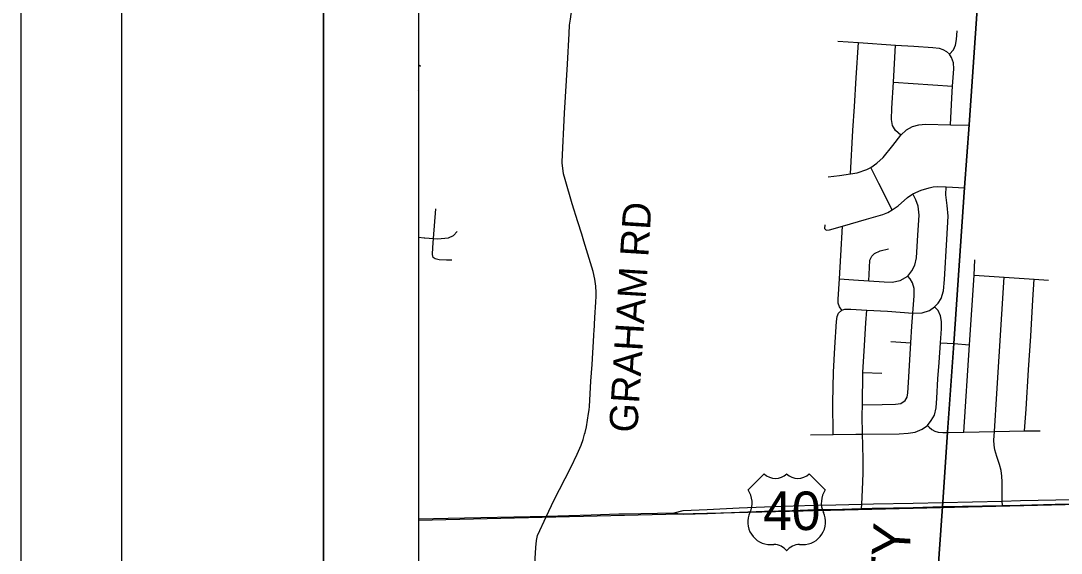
# Model space of a CAD drawing. Extents: x 1880545 to 1948545, y 79309 to 723051.
# Drawn here: x 1880545 to 1890853, y 711978 to 717259 of the extents above; entities that cross this region are included whole.
import ezdxf

# ---------------------------------------------------------------- set-up
doc = ezdxf.new("R2010")
doc.units = 0
for name, color, linetype in [('GM_X_City_Street', 7, 'Continuous'), ('GM_X_County', 7, 'Continuous'), ('GM_X_County_Road', 7, 'Continuous'), ('GM_X_County_Text', 7, 'Continuous'), ('GM_X_Rail_Line', 7, 'Continuous'), ('GM_X_Township', 7, 'Continuous'), ('GM_X_US_Location', 7, 'Continuous'), ('GM_X_US_Route', 7, 'Continuous'), ('GM_X_US_Shield', 7, 'Continuous'), ('SH_Border', 7, 'Continuous'), ('SH_Cut_Line', 7, 'Continuous'), ('SH_Text', 7, 'Continuous')]:
    doc.layers.add(name, color=color, linetype=linetype)

msp = doc.modelspace()

# ---------------------------------------------------------------- linework, layer by layer
at = {"layer": 'GM_X_City_Street'}
for p, q in [((1884485, 716824), (1884504, 716810)), ((1884485, 716572), (1884490, 716578)), ((1889192, 716650), (1889778, 716611)), ((1884633, 715100), (1884658, 715394)), ((1889166, 714079), (1889365, 714065)), ((1889658, 714064), (1889790, 714057)), ((1889790, 714057), (1889944, 714045)), ((1888887, 713769), (1889076, 713763))]:
    msp.add_line(p, q, dxfattribs=at)
for points in [[(1889756, 716227), (1889771, 716494), (1889778, 716611), (1889790, 716782), (1889785, 716843), (1889767, 716893), (1889746, 716927), (1889785, 716970), (1889807, 717017), (1889817, 717073), (1889824, 717159)], [(1888640, 717056), (1888845, 717042), (1889213, 717018), (1889393, 717007), (1889582, 716993), (1889643, 716987), (1889682, 716974), (1889716, 716954), (1889746, 716927)], [(1888765, 715741), (1888790, 716169), (1888805, 716408), (1888823, 716694), (1888845, 717042)], [(1889264, 716123), (1889213, 716169), (1889183, 716220), (1889171, 716281), (1889174, 716391), (1889192, 716650), (1889213, 717018)], [(1888544, 715710), (1888657, 715725), (1888765, 715741), (1888832, 715752), (1888927, 715784), (1888968, 715803), (1889027, 715845), (1889089, 715903), (1889186, 716023), (1889264, 716123), (1889322, 716176), (1889380, 716209), (1889442, 716227), (1889508, 716234), (1889756, 716227), (1889941, 716223)], [(1889177, 715382), (1889046, 715645), (1888968, 715803)], [(1888510, 715236), (1888509, 715200), (1888526, 715183), (1888558, 715184), (1888688, 715221), (1888923, 715291), (1889087, 715338), (1889137, 715358), (1889177, 715382), (1889239, 715423), (1889329, 715507), (1889385, 715542), (1889465, 715580), (1889544, 715602), (1889586, 715611), (1889629, 715614), (1889715, 715613), (1889898, 715601)], [(1889309, 713493), (1889326, 713525), (1889333, 713568), (1889341, 713670), (1889365, 714065), (1889375, 714229), (1889385, 714359), (1889395, 714529), (1889396, 714603), (1889380, 714661), (1889356, 714699), (1889333, 714727), (1889374, 714777), (1889402, 714834), (1889419, 714908), (1889433, 715132), (1889445, 715332), (1889436, 715421), (1889414, 715484), (1889385, 715542)], [(1889528, 713245), (1889566, 713293), (1889597, 713348), (1889615, 713421), (1889621, 713514), (1889632, 713706), (1889643, 713870), (1889658, 714064), (1889666, 714203), (1889668, 714276), (1889659, 714332), (1889633, 714384), (1889599, 714423), (1889634, 714459), (1889664, 714503), (1889687, 714581), (1889696, 714691), (1889721, 715088), (1889733, 715321), (1889723, 715425), (1889712, 715533), (1889715, 715613)], [(1884485, 715114), (1884542, 715107), (1884547, 715106), (1884633, 715100), (1884674, 715097), (1884784, 715107), (1884831, 715129), (1884868, 715169)], [(1888594, 713154), (1888590, 713474), (1888596, 713772), (1888610, 714017), (1888627, 714277), (1888633, 714325), (1888647, 714358), (1888679, 714388), (1888657, 714423), (1888644, 714458), (1888642, 714498), (1888658, 714699), (1888670, 714931), (1888688, 715221)], [(1884817, 714885), (1884763, 714885), (1884689, 714888), (1884650, 714897), (1884632, 714912), (1884625, 714942), (1884626, 715010), (1884633, 715100)], [(1888947, 714680), (1888953, 714812), (1888958, 714883), (1888976, 714925), (1889005, 714950), (1889059, 714977), (1889143, 714996)], [(1889889, 713179), (1889944, 714045), (1889990, 714736), (1889998, 714889)], [(1888658, 714699), (1888795, 714689), (1888947, 714680), (1889100, 714669), (1889178, 714667), (1889258, 714684), (1889333, 714727)], [(1889990, 714736), (1890288, 714716), (1890586, 714696), (1890727, 714685)], [(1890271, 712452), (1890269, 712494), (1890268, 712686), (1890265, 712742), (1890258, 712798), (1890243, 712857), (1890216, 712936), (1890197, 713002), (1890189, 713051), (1890186, 713098), (1890188, 713141), (1890191, 713186), (1890215, 713563), (1890288, 714716)], [(1890491, 713190), (1890505, 713405), (1890530, 713795), (1890553, 714132), (1890572, 714491), (1890586, 714696)], [(1888679, 714388), (1888709, 714397), (1888768, 714400), (1888927, 714388), (1889132, 714378), (1889385, 714359), (1889475, 714363), (1889548, 714386), (1889599, 714423)], [(1888886, 713160), (1888881, 713343), (1888883, 713450), (1888887, 713769), (1888903, 714038), (1888918, 714264), (1888927, 714388)], [(1888883, 713450), (1889078, 713452), (1889213, 713455), (1889266, 713463), (1889309, 713493)], [(1888370, 713152), (1888594, 713154), (1888820, 713160), (1888886, 713160), (1889249, 713163), (1889336, 713167), (1889406, 713177), (1889475, 713209), (1889528, 713245), (1889544, 713228), (1889570, 713205), (1889602, 713188), (1889635, 713178), (1889681, 713174), (1889729, 713175)], [(1889729, 713175), (1889889, 713179), (1890191, 713186), (1890491, 713190), (1890644, 713193)], [(1888874, 712420), (1888877, 712464), (1888885, 712605), (1888891, 712771), (1888890, 712902), (1888888, 713052), (1888886, 713160)]]:
    msp.add_lwpolyline(points, dxfattribs=at)
at = {"layer": 'GM_X_County'}
msp.add_lwpolyline([(1891843, 720212), (1891817, 719823), (1890200, 719967), (1890150, 719243), (1889940, 716226), (1889896, 715604), (1889789, 714059), (1889789, 714057), (1889728, 713178), (1889728, 713177), (1889680, 712485), (1889677, 712442), (1889513, 710095), (1889456, 709272), (1889272, 706620), (1886741, 706793), (1884485, 706947)], dxfattribs=at)
at = {"layer": 'GM_X_County_Road'}
for points in [[(1885910, 715859), (1885931, 716341), (1885961, 716830), (1885977, 717132), (1885983, 717214), (1885990, 717276), (1885998, 717324), (1886014, 717394), (1886028, 717448), (1886144, 717890), (1886191, 718072), (1886206, 718189), (1886290, 718819), (1886327, 719099), (1886346, 719310)], [(1886102, 715143), (1886064, 715266), (1886009, 715444), (1885939, 715686), (1885923, 715741), (1885916, 715798), (1885910, 715848), (1885910, 715859)], [(1886245, 714528), (1886246, 714565), (1886243, 714628), (1886233, 714695), (1886215, 714773), (1886124, 715072), (1886102, 715143)], [(1886224, 714158), (1886225, 714178), (1886232, 714316), (1886243, 714469), (1886245, 714528)], [(1886131, 713159), (1886135, 713174), (1886151, 713232), (1886161, 713297), (1886171, 713362), (1886176, 713400), (1886178, 713432), (1886193, 713684), (1886206, 713850), (1886222, 714138), (1886224, 714158)], [(1885752, 712346), (1885826, 712499), (1885996, 712828), (1886059, 712960), (1886096, 713049), (1886117, 713107), (1886131, 713159)], [(1885497, 709679), (1885500, 709732), (1885560, 710632), (1885590, 711101), (1885614, 711485), (1885625, 711631), (1885630, 711768), (1885647, 712035), (1885654, 712104), (1885664, 712154), (1885752, 712346)]]:
    msp.add_lwpolyline(points, dxfattribs=at)
at = {"layer": 'GM_X_Rail_Line'}
msp.add_line((1884485, 712304), (1889656, 712431), dxfattribs=at)
msp.add_lwpolyline([(1889656, 712431), (1890757, 712458), (1898417, 712647), (1903434, 712741), (1904816, 712771), (1913576, 712916), (1914801, 712916), (1920019, 712995), (1921942, 713063), (1924553, 713124), (1928206, 713206)], dxfattribs=at)
at = {"layer": 'GM_X_Township'}
for points in [[(1886104, 720212), (1886445, 720189), (1890200, 719967), (1890150, 719243), (1889940, 716226), (1889896, 715604), (1889789, 714059), (1889789, 714057), (1889728, 713178), (1889728, 713177), (1889680, 712485), (1889677, 712442), (1889513, 710095), (1889456, 709272), (1889272, 706620), (1886741, 706793), (1884485, 706947)], [(1889272, 706620), (1889456, 709272), (1889513, 710095), (1889677, 712442), (1889680, 712485), (1889728, 713177), (1889728, 713178), (1889789, 714057), (1889789, 714059), (1889896, 715604), (1889940, 716226), (1890150, 719243), (1890200, 719967), (1891817, 719823), (1893081, 719771), (1893522, 719763), (1894775, 719644), (1896793, 719532), (1896834, 719533), (1897456, 719507), (1898145, 719477), (1899877, 719378), (1904377, 719099)]]:
    msp.add_lwpolyline(points, dxfattribs=at)
at = {"layer": 'GM_X_US_Route'}
for p, q in [((1886524, 712369), (1886853, 712376)), ((1886853, 712376), (1887017, 712379)), ((1887017, 712379), (1887071, 712370))]:
    msp.add_line(p, q, dxfattribs=at)
for points in [[(1887017, 712379), (1887108, 712402), (1887345, 712413), (1887664, 712428), (1887915, 712438), (1888197, 712448), (1888425, 712453), (1888621, 712456), (1888877, 712464), (1888995, 712467), (1889387, 712475), (1889681, 712482)], [(1889678, 712440), (1890271, 712452), (1890446, 712455), (1890795, 712464), (1891094, 712470)], [(1889681, 712482), (1890269, 712494), (1890450, 712499), (1890799, 712508), (1891114, 712515), (1891398, 712520), (1891508, 712522)], [(1884485, 712318), (1884778, 712324), (1885752, 712346), (1886197, 712357), (1886469, 712368)], [(1886469, 712368), (1886475, 712368), (1886524, 712369)], [(1887071, 712370), (1887108, 712364), (1887349, 712372), (1887666, 712384), (1887912, 712394), (1888187, 712403), (1888423, 712410), (1888590, 712413), (1888874, 712420), (1888982, 712424)], [(1888982, 712424), (1888992, 712424), (1889388, 712432), (1889678, 712440)]]:
    msp.add_lwpolyline(points, dxfattribs=at)
at = {"layer": 'GM_X_US_Shield'}
for p, q in [((1887910, 712765), (1887751, 712606)), ((1888516, 712606), (1888357, 712765)), ((1887974, 712063), (1888006, 712063)), ((1888261, 712063), (1888293, 712063))]:
    msp.add_line(p, q, dxfattribs=at)
for centre, radius, start, end in [((1888022, 712879), 160, 225.573, 314.427), ((1888245, 712879), 160, 225.573, 314.427), ((1887568, 712477), 223, 334.5471, 35.0009), ((1888699, 712477), 223, 144.9991, 205.4529), ((1887971, 712287), 223, 154.8319, 270.6383), ((1888295, 712287), 223, 269.3617, 25.1681), ((1888006, 711904), 160, 36.8699, 90), ((1888261, 711904), 160, 90, 143.1301)]:
    msp.add_arc(centre, radius, start, end, dxfattribs=at)
at = {"layer": 'SH_Border'}
for points in [[(1881545, 722051), (1883545, 722051), (1883545, 680051), (1881545, 680051)], [(1883545, 722051), (1947545, 722051), (1947545, 680051), (1883545, 680051)]]:
    msp.add_lwpolyline(points, close=True, dxfattribs=at)
at = {"layer": 'SH_Cut_Line'}
msp.add_lwpolyline([(1880545, 679051), (1948545, 679051), (1948545, 723051), (1880545, 723051)], close=True, dxfattribs=at)
at = {"layer": 'SH_Text'}
msp.add_lwpolyline([(1884490, 720381), (1928141, 720381), (1928141, 691152), (1884490, 691152)], close=True, dxfattribs=at)

# ---------------------------------------------------------------- texts
at = {"layer": 'GM_X_County_Text'}
msp.add_text('FRANKLIN COUNTY', height=375, rotation=86.3996, dxfattribs=at).set_placement((1889072, 707537))
at = {"layer": 'GM_X_US_Location'}
for s in ['0', '/']:
    msp.add_text(s, height=1, dxfattribs=at).set_placement((1888095, 712414))
msp.add_text('40', height=1, rotation=0, dxfattribs=at).set_placement((1887888, 712207))
at = {"layer": 'GM_X_US_Shield'}
msp.add_text('40', height=382.9, dxfattribs=at).set_placement((1887899, 712207))
at = {"layer": 'SH_Text'}
msp.add_text('GRAHAM RD', height=280, rotation=86.4008, dxfattribs=at).set_placement((1886652, 713168))

doc.saveas('drawing.dxf')
